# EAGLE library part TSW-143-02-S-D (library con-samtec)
THROUGH-HOLE .025" SQ POST HEADER Source: Samtec TSW.pdf
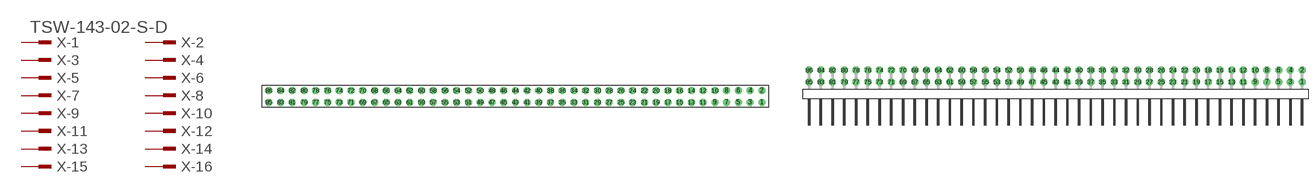
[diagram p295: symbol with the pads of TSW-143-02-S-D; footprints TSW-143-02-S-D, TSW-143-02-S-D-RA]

Designator prefix X; gates -1=MPINV -2=MPIN -3=MPIN -4=MPIN -5=MPIN -6=MPIN -7=MPIN -8=MPIN -9=MPIN -10=MPIN -11=MPIN -12=MPIN -13=MPIN -14=MPIN -15=MPIN -16=MPIN -17=MPIN -18=MPIN -19=MPIN -20=MPIN -21=MPIN -22=MPIN -23=MPIN -24=MPIN -25=MPIN -26=MPIN -27=MPIN -28=MPIN -29=MPIN -30=MPIN -31=MPIN -32=MPIN -33=MPIN -34=MPIN -35=MPIN -36=MPIN -37=MPIN -38=MPIN -39=MPIN -40=MPIN -41=MPIN -42=MPIN -43=MPIN -44=MPIN -45=MPIN -46=MPIN -47=MPIN -48=MPIN -49=MPIN -50=MPIN -51=MPIN -52=MPIN -53=MPIN -54=MPIN -55=MPIN -56=MPIN -57=MPIN -58=MPIN -59=MPIN -60=MPIN -61=MPIN -62=MPIN -63=MPIN -64=MPIN -65=MPIN -66=MPIN -67=MPIN -68=MPIN -69=MPIN -70=MPIN -71=MPIN -72=MPIN -73=MPIN -74=MPIN -75=MPIN -76=MPIN -77=MPIN -78=MPIN -79=MPIN -80=MPIN -81=MPIN -82=MPIN -83=MPIN -84=MPIN -85=MPIN -86=MPIN

## TSW-143-02-S-D (OC_FARNELL: unknown; OC_NEWARK: unknown)  [TSW-143-02-S-D]
1  -1:1  pas
2  -2:1  pas
3  -3:1  pas
4  -4:1  pas
5  -5:1  pas
6  -6:1  pas
7  -7:1  pas
8  -8:1  pas
9  -9:1  pas
10  -10:1  pas
11  -11:1  pas
12  -12:1  pas
13  -13:1  pas
14  -14:1  pas
15  -15:1  pas
16  -16:1  pas
17  -17:1  pas
18  -18:1  pas
19  -19:1  pas
20  -20:1  pas
21  -21:1  pas
22  -22:1  pas
23  -23:1  pas
24  -24:1  pas
25  -25:1  pas
26  -26:1  pas
27  -27:1  pas
28  -28:1  pas
29  -29:1  pas
30  -30:1  pas
31  -31:1  pas
32  -32:1  pas
33  -33:1  pas
34  -34:1  pas
35  -35:1  pas
36  -36:1  pas
37  -37:1  pas
38  -38:1  pas
39  -39:1  pas
40  -40:1  pas
41  -41:1  pas
42  -42:1  pas
43  -43:1  pas
44  -44:1  pas
45  -45:1  pas
46  -46:1  pas
47  -47:1  pas
48  -48:1  pas
49  -49:1  pas
50  -50:1  pas
51  -51:1  pas
52  -52:1  pas
53  -53:1  pas
54  -54:1  pas
55  -55:1  pas
56  -56:1  pas
57  -57:1  pas
58  -58:1  pas
59  -59:1  pas
60  -60:1  pas
61  -61:1  pas
62  -62:1  pas
63  -63:1  pas
64  -64:1  pas
65  -65:1  pas
66  -66:1  pas
67  -67:1  pas
68  -68:1  pas
69  -69:1  pas
70  -70:1  pas
71  -71:1  pas
72  -72:1  pas
73  -73:1  pas
74  -74:1  pas
75  -75:1  pas
76  -76:1  pas
77  -77:1  pas
78  -78:1  pas
79  -79:1  pas
80  -80:1  pas
81  -81:1  pas
82  -82:1  pas
83  -83:1  pas
84  -84:1  pas
85  -85:1  pas
86  -86:1  pas

## TSW-143-02-S-D-RA (OC_FARNELL: unknown; OC_NEWARK: unknown)  [TSW-143-02-S-D-RA]
Pads as for TSW-143-02-S-D

## Footprint TSW-143-02-S-D (pad centres in mm)
THROUGH-HOLE .025" SQ POST HEADER Source: Samtec TSW.pdf
drill 1 pad 1.5 octagon: 1 53.34,-1.27; 2 53.34,1.27; 3 50.8,-1.27; 4 50.8,1.27; 5 48.26,-1.27; 6 48.26,1.27; 7 45.72,-1.27; 8 45.72,1.27; 9 43.18,-1.27; 10 43.18,1.27; 11 40.64,-1.27; 12 40.64,1.27; 13 38.1,-1.27; 14 38.1,1.27; 15 35.56,-1.27; 16 35.56,1.27; 17 33.02,-1.27; 18 33.02,1.27; 19 30.48,-1.27; 20 30.48,1.27; 21 27.94,-1.27; 22 27.94,1.27; 23 25.4,-1.27; 24 25.4,1.27; 25 22.86,-1.27; 26 22.86,1.27; 27 20.32,-1.27; 28 20.32,1.27; 29 17.78,-1.27; 30 17.78,1.27; 31 15.24,-1.27; 32 15.24,1.27; 33 12.7,-1.27; 34 12.7,1.27; 35 10.16,-1.27; 36 10.16,1.27; 37 7.62,-1.27; 38 7.62,1.27; 39 5.08,-1.27; 40 5.08,1.27; 41 2.54,-1.27; 42 2.54,1.27; 43 0,-1.27; 44 0,1.27; 45 -2.54,-1.27; 46 -2.54,1.27; 47 -5.08,-1.27; 48 -5.08,1.27; 49 -7.62,-1.27; 50 -7.62,1.27; 51 -10.16,-1.27; 52 -10.16,1.27; 53 -12.7,-1.27; 54 -12.7,1.27; 55 -15.24,-1.27; 56 -15.24,1.27; 57 -17.78,-1.27; 58 -17.78,1.27; 59 -20.32,-1.27; 60 -20.32,1.27; 61 -22.86,-1.27; 62 -22.86,1.27; 63 -25.4,-1.27; 64 -25.4,1.27; 65 -27.94,-1.27; 66 -27.94,1.27; 67 -30.48,-1.27; 68 -30.48,1.27; 69 -33.02,-1.27; 70 -33.02,1.27; 71 -35.56,-1.27; 72 -35.56,1.27; 73 -38.1,-1.27; 74 -38.1,1.27; 75 -40.64,-1.27; 76 -40.64,1.27; 77 -43.18,-1.27; 78 -43.18,1.27; 79 -45.72,-1.27; 80 -45.72,1.27; 81 -48.26,-1.27; 82 -48.26,1.27; 83 -50.8,-1.27; 84 -50.8,1.27; 85 -53.34,-1.27; 86 -53.34,1.27

## Footprint TSW-143-02-S-D-RA (pad centres in mm)
THROUGH-HOLE .025" SQ POST HEADER Source: Samtec TSW.pdf
drill 1 pad 1.5 octagon: 1 53.34,1.524; 2 53.34,4.064; 3 50.8,1.524; 4 50.8,4.064; 5 48.26,1.524; 6 48.26,4.064; 7 45.72,1.524; 8 45.72,4.064; 9 43.18,1.524; 10 43.18,4.064; 11 40.64,1.524; 12 40.64,4.064; 13 38.1,1.524; 14 38.1,4.064; 15 35.56,1.524; 16 35.56,4.064; 17 33.02,1.524; 18 33.02,4.064; 19 30.48,1.524; 20 30.48,4.064; 21 27.94,1.524; 22 27.94,4.064; 23 25.4,1.524; 24 25.4,4.064; 25 22.86,1.524; 26 22.86,4.064; 27 20.32,1.524; 28 20.32,4.064; 29 17.78,1.524; 30 17.78,4.064; 31 15.24,1.524; 32 15.24,4.064; 33 12.7,1.524; 34 12.7,4.064; 35 10.16,1.524; 36 10.16,4.064; 37 7.62,1.524; 38 7.62,4.064; 39 5.08,1.524; 40 5.08,4.064; 41 2.54,1.524; 42 2.54,4.064; 43 0,1.524; 44 0,4.064; 45 -2.54,1.524; 46 -2.54,4.064; 47 -5.08,1.524; 48 -5.08,4.064; 49 -7.62,1.524; 50 -7.62,4.064; 51 -10.16,1.524; 52 -10.16,4.064; 53 -12.7,1.524; 54 -12.7,4.064; 55 -15.24,1.524; 56 -15.24,4.064; 57 -17.78,1.524; 58 -17.78,4.064; 59 -20.32,1.524; 60 -20.32,4.064; 61 -22.86,1.524; 62 -22.86,4.064; 63 -25.4,1.524; 64 -25.4,4.064; 65 -27.94,1.524; 66 -27.94,4.064; 67 -30.48,1.524; 68 -30.48,4.064; 69 -33.02,1.524; 70 -33.02,4.064; 71 -35.56,1.524; 72 -35.56,4.064; 73 -38.1,1.524; 74 -38.1,4.064; 75 -40.64,1.524; 76 -40.64,4.064; 77 -43.18,1.524; 78 -43.18,4.064; 79 -45.72,1.524; 80 -45.72,4.064; 81 -48.26,1.524; 82 -48.26,4.064; 83 -50.8,1.524; 84 -50.8,4.064; 85 -53.34,1.524; 86 -53.34,4.064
